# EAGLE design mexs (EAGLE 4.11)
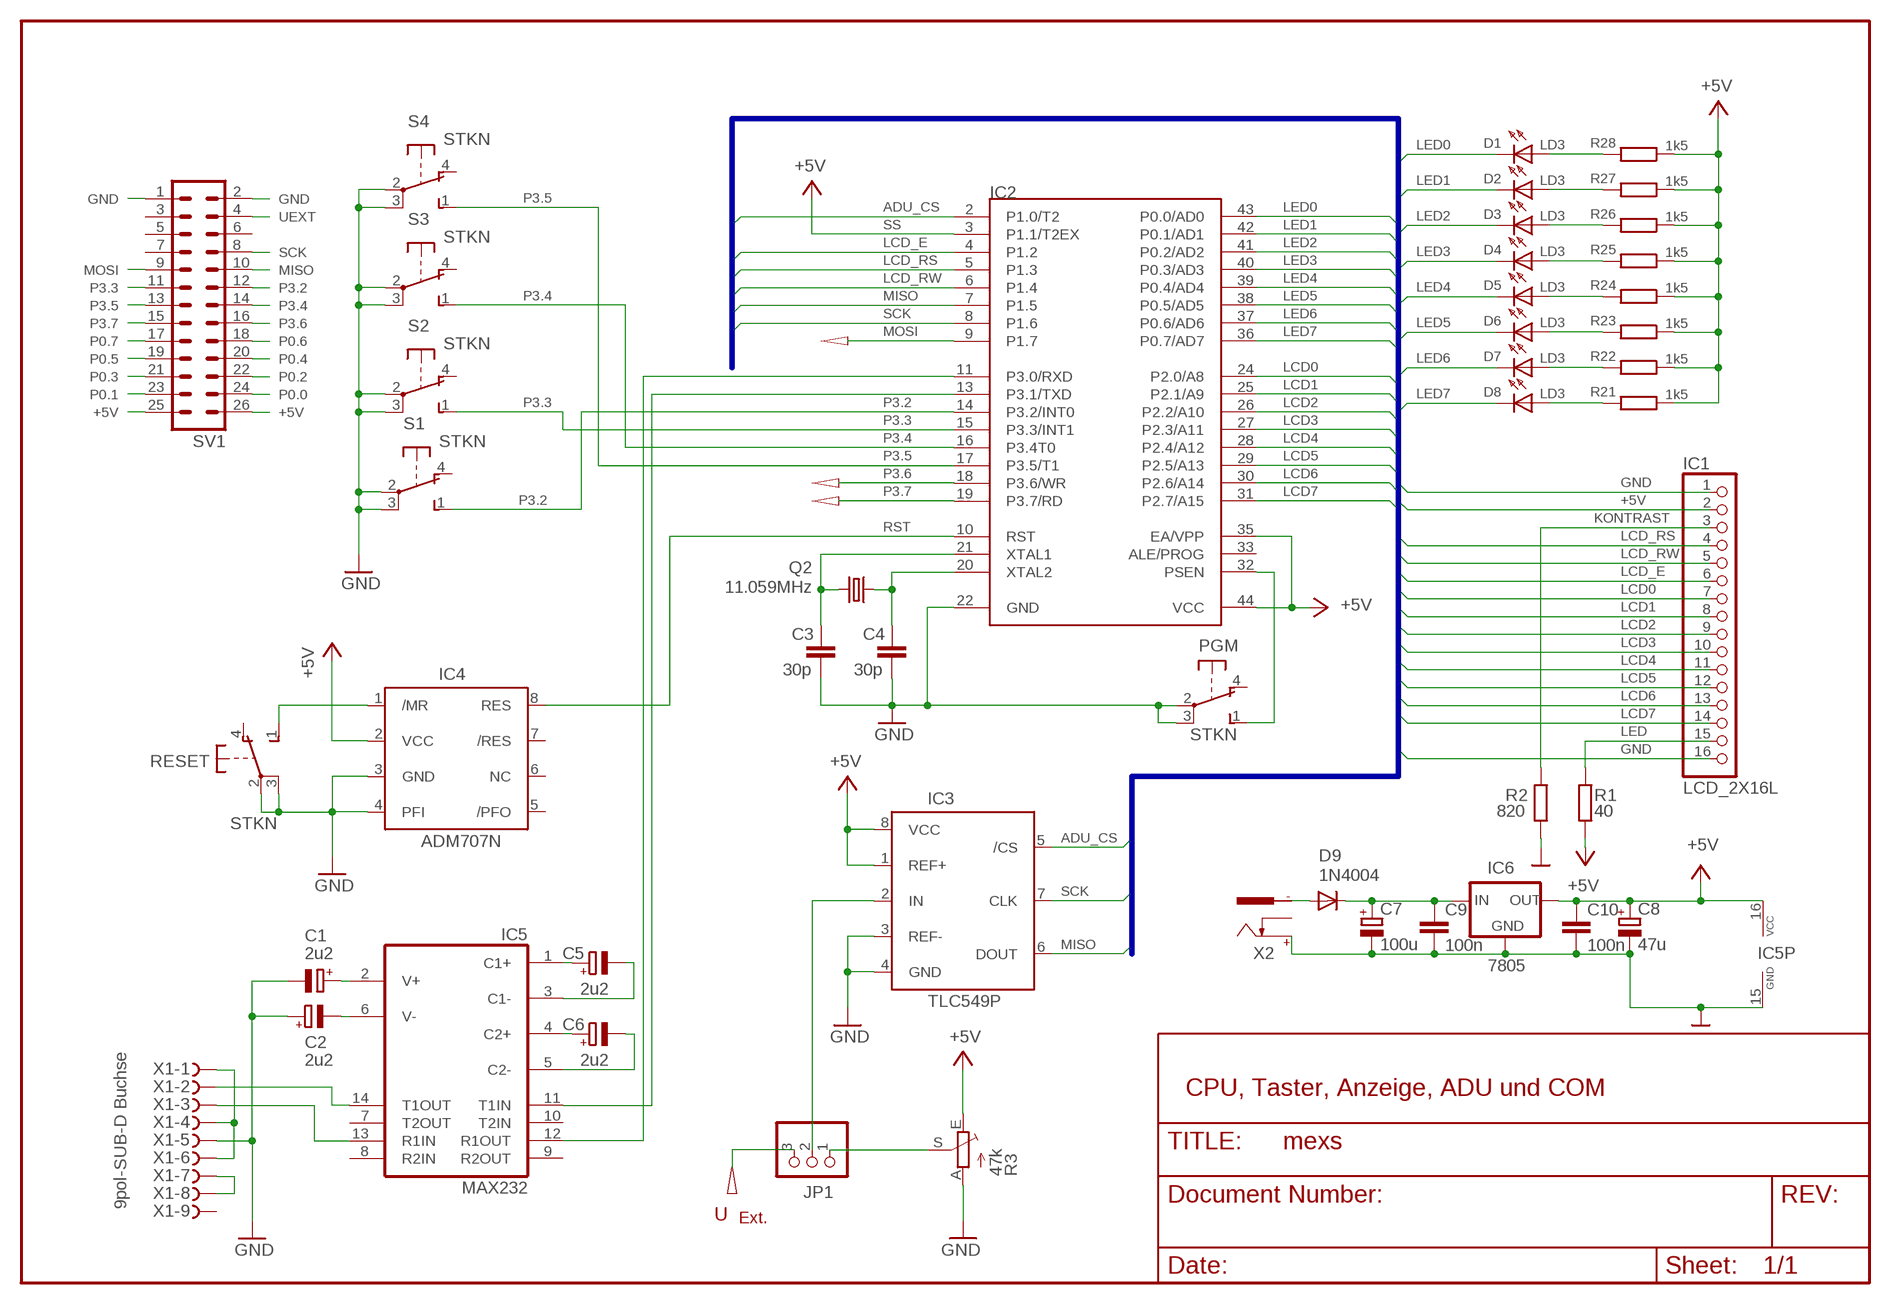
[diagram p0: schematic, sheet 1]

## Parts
C1  2u2  CPOL-EUE2.5-5  [E2,5-5]
C2  2u2  CPOL-EUE2.5-5  [E2,5-5]
C3  30p  C-EU025-024X044  [C025-024X044]
C4  30p  C-EU025-024X044  [C025-024X044]
C5  2u2  CPOL-EUE2.5-5  [E2,5-5]
C6  2u2  CPOL-EUE2.5-5  [E2,5-5]
C7  100u  CPOL-EUE5-10.5  [E5-10,5]
C8  47u  CPOL-EUE5-10.5  [E5-10,5]
C9  100n  C-EU050-025X075  [C050-025X075]
C10  100n  C-EU050-025X075  [C050-025X075]
D1  LD3  LED3MM  [LED3MM]
D2  LD3  LED3MM  [LED3MM]
D3  LD3  LED3MM  [LED3MM]
D4  LD3  LED3MM  [LED3MM]
D5  LD3  LED3MM  [LED3MM]
D6  LD3  LED3MM  [LED3MM]
D7  LD3  LED3MM  [LED3MM]
D8  LD3  LED3MM  [LED3MM]
D9  1N4004  [DO41-10]
IC1  LCD_2X16L  [LCD2X16]
IC2  AT89C55P  [PLCC44PA]
IC3  TLC549P  [DIL08]
IC4  ADM707N  [DIL08]
IC5  MAX232  [DIL16]
IC6  7805  78XXL  [78XXL]
JP1  PINHD-1X3  [1X03]
PGM  STKN  [STK-SCHMAL]
Q2  11.059MHz  CRYTALHC49U-V  [HC49U-V]
R1  40  R-EU_0207/7FETT  [0207/7FETT]
R2  820  R-EU_0207/7FETT  [0207/7FETT]
R3  47k  TRIM_EU-LI15  [LI15]
R21  1k5  R-EU_0207/7  [0207/7]
R22  1k5  R-EU_0207/7  [0207/7]
R23  1k5  R-EU_0207/7  [0207/7]
R24  1k5  R-EU_0207/7  [0207/7]
R25  1k5  R-EU_0207/7  [0207/7]
R26  1k5  R-EU_0207/7  [0207/7]
R27  1k5  R-EU_0207/7  [0207/7]
R28  1k5  R-EU_0207/7  [0207/7]
RESET  STKN  [STK-SCHMAL]
S1  STKN  [STK-SCHMAL]
S2  STKN  [STK-SCHMAL]
S3  STKN  [STK-SCHMAL]
S4  STKN  [STK-SCHMAL]
SV1  ML26  [ML26]
X1  9pol-SUB-D Buchse  F09HS  [F09H]
X2  737992-55  [737992-5]

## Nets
+5V: C8.+ C10.1 IC1.2 IC2.3(P1.1/T2EX) IC2.35(EA/VPP) IC2.44(VCC) IC3.1(REF+) IC3.8(VCC) IC4.2(VCC) IC5.16(VCC) IC6.OUT R1.1 R3.E R21.1 R22.1 R23.1 R24.1 R25.1 R26.1 R27.1 R28.1 SV1.25 SV1.26
ADU_CS: IC2.2(P1.0/T2) IC3.5(/CS)
GND: C1.- C2.+ C3.2 C4.2 C7.- C8.- C9.2 C10.2 IC1.1 IC1.16 IC2.22(GND) IC3.3(REF-) IC3.4(GND) IC4.3(GND) IC4.4(PFI) IC5.15(GND) IC6.GND PGM.2(P) PGM.3(P) R2.1 R3.A RESET.2(P) RESET.3(P) S1.2(P) S1.3(P) S2.2(P) S2.3(P) S3.2(P) S3.3(P) S4.2(P) S4.3(P) SV1.1 SV1.2 X1.5 X2.+
KONTRAST: IC1.3 R2.2
LCD0: IC1.7 IC2.24(P2.0/A8)
LCD1: IC1.8 IC2.25(P2.1/A9)
LCD2: IC1.9 IC2.26(P2.2/A10)
LCD3: IC1.10 IC2.27(P2.3/A11)
LCD4: IC1.11 IC2.28(P2.4/A12)
LCD5: IC1.12 IC2.29(P2.5/A13)
LCD6: IC1.13 IC2.30(P2.6/A14)
LCD7: IC1.14 IC2.31(P2.7/A15)
LCD_E: IC1.6 IC2.4(P1.2)
LCD_RS: IC1.4 IC2.5(P1.3)
LCD_RW: IC1.5 IC2.6(P1.4)
LED: IC1.15 R1.2
LED0: D1.K(C) IC2.43(P0.0/AD0) SV1.24
LED1: D2.K(C) IC2.42(P0.1/AD1) SV1.23
LED2: D3.K(C) IC2.41(P0.2/AD2) SV1.22
LED3: D4.K(C) IC2.40(P0.3/AD3) SV1.21
LED4: D5.K(C) IC2.39(P0.4/AD4) SV1.20
LED5: D6.K(C) IC2.38(P0.5/AD5) SV1.19
LED6: D7.K(C) IC2.37(P0.6/AD6) SV1.18
LED7: D8.K(C) IC2.36(P0.7/AD7) SV1.17
MISO: IC2.7(P1.5) IC3.6(DOUT) SV1.10
MOSI: IC2.9(P1.7) SV1.9
N$1: C3.1 IC2.21(XTAL1) Q2.2
N$2: C4.1 IC2.20(XTAL2) Q2.1
N$3: X1.1 X1.4 X1.6
N$4: IC4.1(/MR) RESET.1(S)
N$5: IC3.2(IN) JP1.2
N$6: D9.A X2.-1
N$7: IC2.32(PSEN) PGM.1(S)
N$8: D8.A R21.2
N$9: X1.7 X1.8
N$10: C7.+ C9.1 D9.C IC6.IN
N$11: IC5.14(T1OUT) X1.2
N$12: IC5.13(R1IN) X1.3
N$13: D7.A R22.2
N$14: D6.A R23.2
N$15: IC2.11(P3.0/RXD) IC5.12(R1OUT)
N$16: D5.A R24.2
N$17: D4.A R25.2
N$18: D3.A R26.2
N$19: D2.A R27.2
N$20: D1.A R28.2
N$21: IC2.13(P3.1/TXD) IC5.11(T1IN)
N$22: C5.+ IC5.1(C1+)
N$23: C6.+ IC5.4(C2+)
N$24: C5.- IC5.3(C1-)
N$25: C6.- IC5.5(C2-)
N$26: C2.- IC5.6(V-)
N$27: C1.+ IC5.2(V+)
N$28: JP1.1 R3.S
P3.2: IC2.14(P3.2/INT0) S1.1(S) SV1.12
P3.3: IC2.15(P3.3/INT1) S2.1(S) SV1.11
P3.4: IC2.16(P3.4T0) S3.1(S) SV1.14
P3.5: IC2.17(P3.5/T1) S4.1(S) SV1.13
P3.6: IC2.18(P3.6/WR) SV1.16
P3.7: IC2.19(P3.7/RD) SV1.15
RST: IC2.10(RST) IC4.8(RES)
SCK: IC2.8(P1.6) IC3.7(CLK) SV1.8
UEXT: JP1.3 SV1.4
Unconnected: IC2.33(ALE/PROG) IC4.5(/PFO) IC4.6(NC) IC4.7(/RES) IC5.7(T2OUT) IC5.8(R2IN) IC5.9(R2OUT) IC5.10(T2IN) PGM.4(O) RESET.4(O) S1.4(O) S2.4(O) S3.4(O) S4.4(O) SV1.3 SV1.5 SV1.6 SV1.7 X1.9 X2.-2 X2.K

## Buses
LCD[0..7],LCD_E,LCD_RS,LCD_RW,+5V,GND,SCK,MOSI,MISO,RES,LED[0..7],P1.[0..7]

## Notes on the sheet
- SS
- P0.7 | P0.6
- P0.5 | P0.4
- P0.3 | P0.2
- P0.1 | P0.0
- CPU, Taster, Anzeige, ADU und COM
- Ext.
- U

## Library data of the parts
C1 C2 C5-C8 = rcl:CPOL-EU: POLARIZED CAPACITOR, European symbol
C3 C4 C9 C10 = rcl:C-EU: CAPACITOR, European symbol
D1-D8 = led:LED3MM: LED
D9 = diode:1N4004: DIODE
IC1 = display-lcd:LCD_2X16: LC-Display mit 2 Zeilen a 16 Zeichen. Anschluss per 14 poligem Standard-Interface.
IC2 = atmel89cxxxx:AT89C55P
IC3 = linear:TLC549: 8-Bit Analog-Digital Umsetzer mit SPI-Schnittstelle, 5 V, CMOS
IC4 = analog-devices:ADM707: uC Supervisor
IC5 = maxim:MAX232: RS232 TRANSEIVER
IC6 = v-reg:78XXL: VOLTAGE REGULATOR
JP1 = pinhead:PINHD-1X3: PIN HEADER
PGM RESET S1-S4 = switch-misc:STK: SWITCH
Q2 = crystal:CRYTAL: CRYSTAL
R1 R2 R21-R28 = rcl:R-EU_: RESISTOR, European symbol
R3 = pot:TRIM_EU-: POTENTIOMETER
SV1 = con-ml:ML26: HARTING
X1 = con-subd:F09?S: SUB-D
X2 = con-conrad:737992-55: FEMALE PRINT CONNECTOR DIN 45323 (34V/3A), ROKA, distributor Conrad

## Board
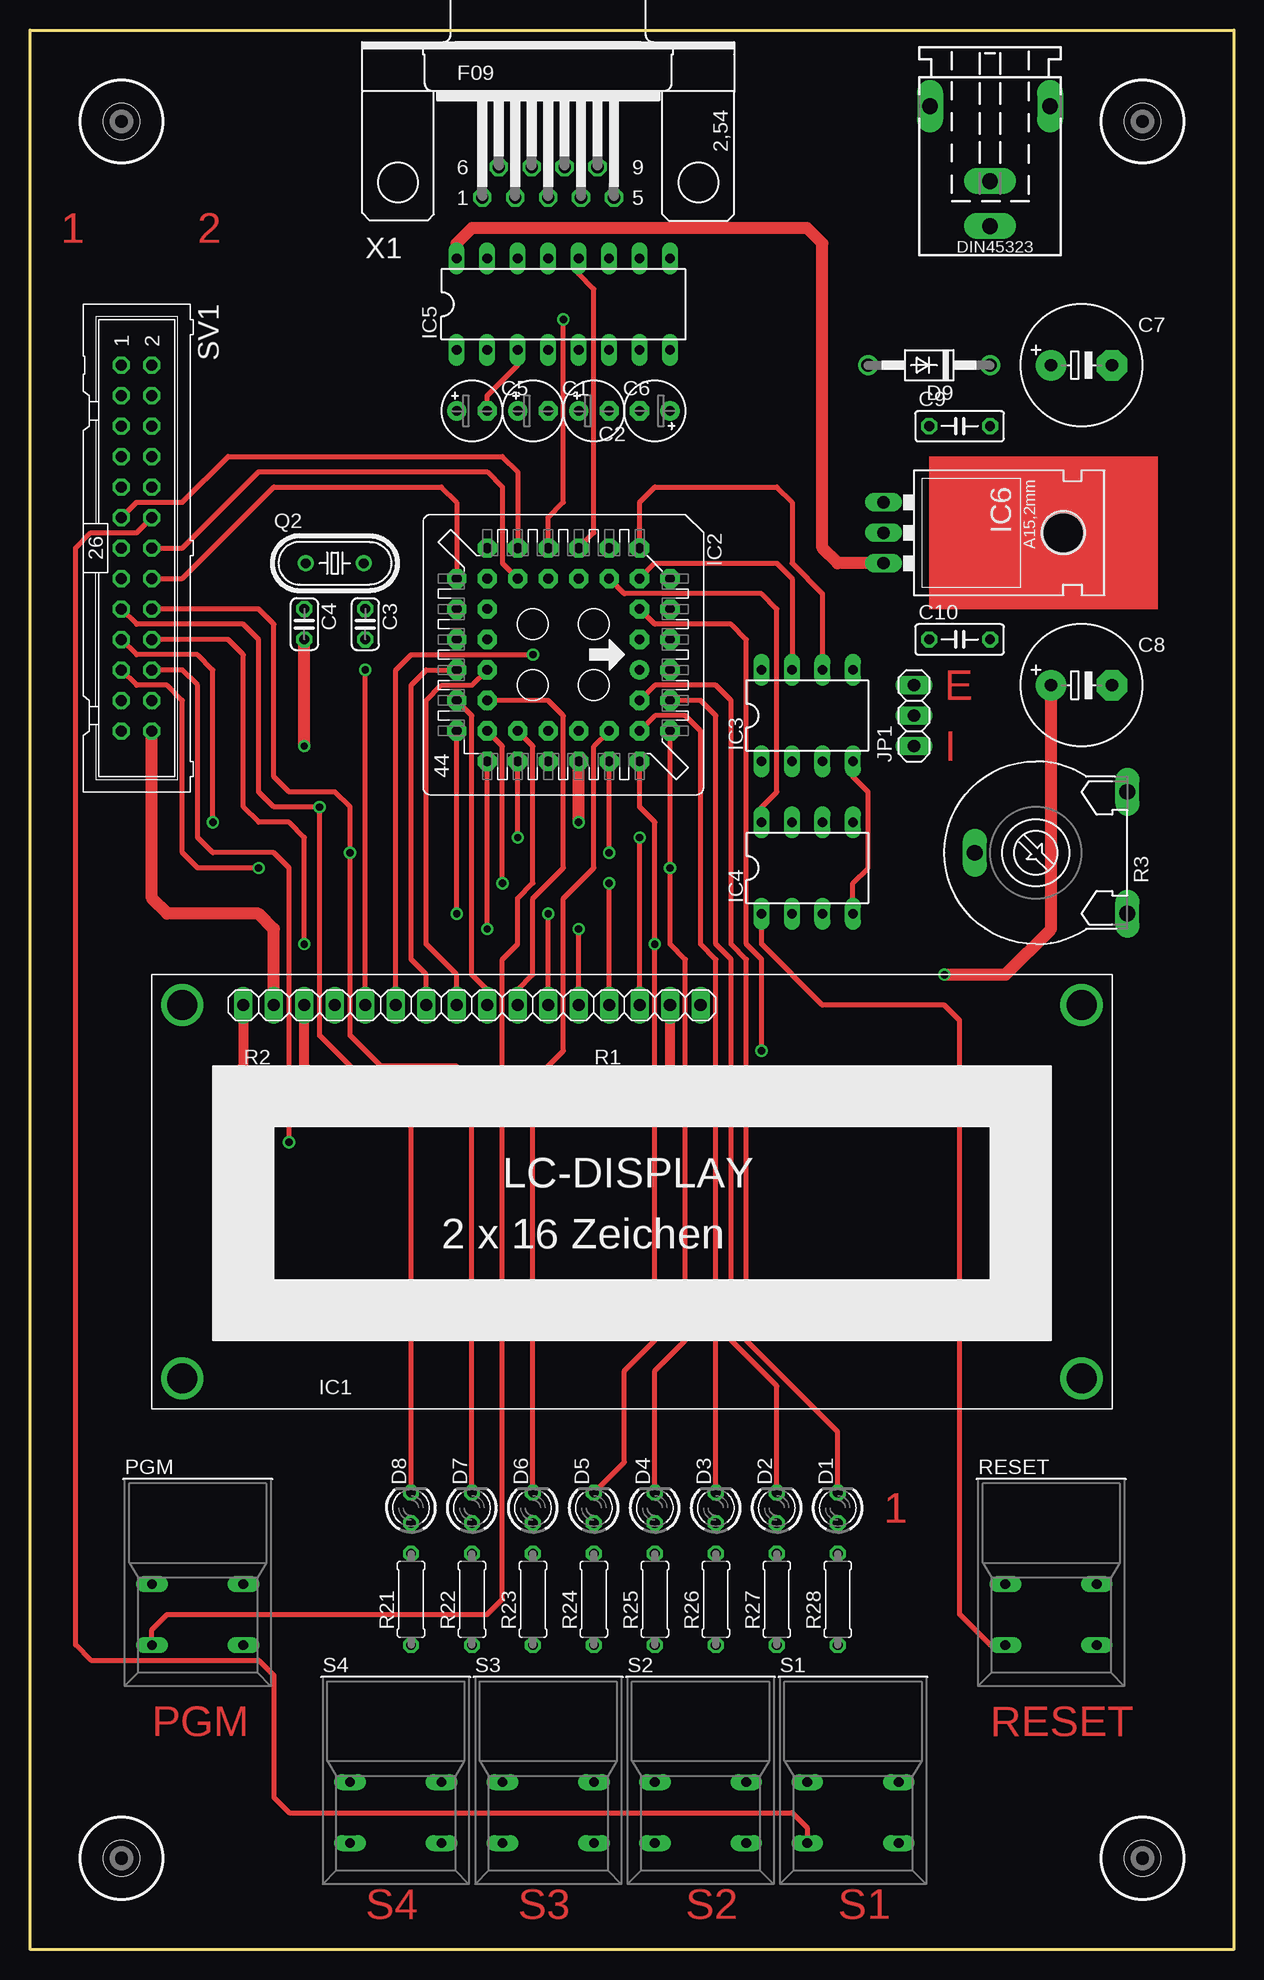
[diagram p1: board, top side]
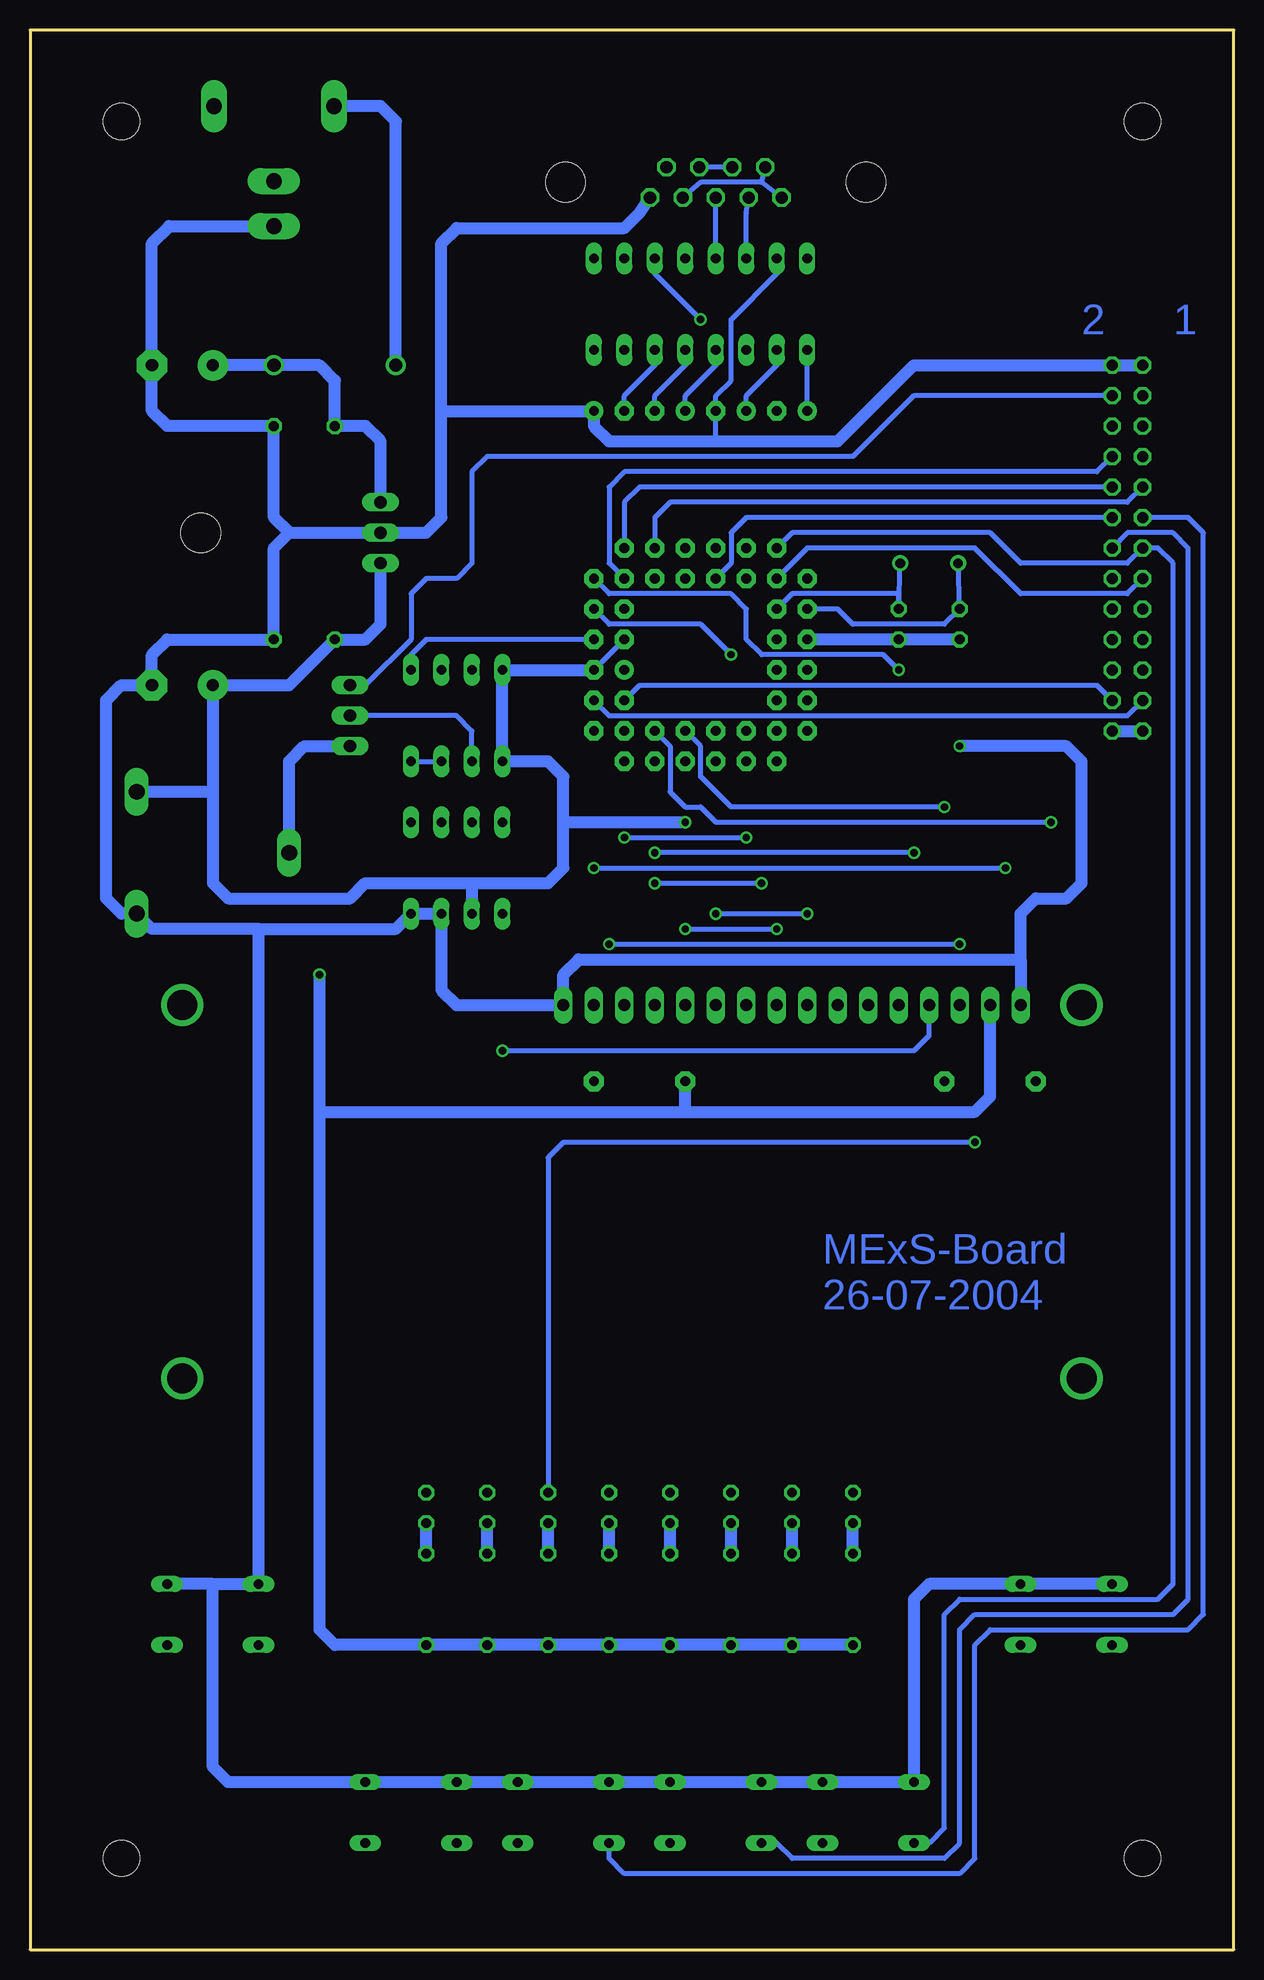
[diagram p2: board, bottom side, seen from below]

Size 100.33 x 160.02 mm. Coordinates in mm from the lower left corner, seen from the top.
Outline: 0,0 0,160.02 100.33,160.02 100.33,0 0,0
Copper layers (1*16): Top 0.035mm / dielectric 1.5mm / Bottom 0.035mm
Design rules "default": minimum track width 16mil, minimum drill 24mil, track to track 8mil, track to pad 8mil, pad to pad 8mil, via to via 8mil, smd to smd 8mil, copper to edge 40mil, drill to drill 8mil, minimum pad ring 10mil, minimum via ring 8mil, stop-mask expansion 4mil, vias tented up to drill 0mil, thermal gap 10mil

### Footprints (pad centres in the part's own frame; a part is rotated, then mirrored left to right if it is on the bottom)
E2,5-5 = drill 0.813 pad 1.6 round: + -1.27,0 | drill 0.813 pad 1.6 octagon: - 1.27,0
C025-024X044 = drill 0.813 octagon: 1 -1.27,0; 2 1.27,0
E5-10,5 = drill 1.016 pad 2.54 round: + -2.54,0 | drill 1.016 pad 2.54 octagon: - 2.54,0
C050-025X075 = drill 0.813 octagon: 1 -2.54,0; 2 2.54,0
LED3MM = drill 0.813 octagon: A -1.27,0; K 1.27,0
DO41-10 = drill 1.118 round: A 5.08,0; C -5.08,0
LCD2X16 = drill 1.016 long: 1 -20.32,7.62; 2 -17.78,7.62; 3 -15.24,7.62; 4 -12.7,7.62; 5 -10.16,7.62; 6 -7.62,7.62; 7 -5.08,7.62; 8 -2.54,7.62; 9 0,7.62; 10 2.54,7.62; 11 5.08,7.62; 12 7.62,7.62; 13 10.16,7.62; 14 12.7,7.62; 15 15.24,7.62; 16 17.78,7.62 | drill 2.5 round: P$1 -25.4,7.62; P$2 49.53,7.62; P$3 -25.4,-23.495; P$4 49.53,-23.495
PLCC44PA = drill 0.813 pad 1.6 round: 1 1.27,6.35 | drill 0.813 pad 1.6 octagon: 2 -1.27,8.89; 3 -1.27,6.35; 4 -3.81,8.89; 5 -3.81,6.35; 6 -6.35,8.89; 7 -8.89,6.35; 8 -6.35,6.35; 9 -8.89,3.81; 10 -6.35,3.81; 11 -8.89,1.27; 12 -6.35,1.27; 13 -8.89,-1.27; 14 -6.35,-1.27; 15 -8.89,-3.81; 16 -6.35,-3.81; 17 -8.89,-6.35; 18 -6.35,-8.89; 19 -6.35,-6.35; 20 -3.81,-8.89; 21 -3.81,-6.35; 22 -1.27,-8.89; 23 -1.27,-6.35; 24 1.27,-8.89; 25 1.27,-6.35; 26 3.81,-8.89; 27 3.81,-6.35; 28 6.35,-8.89; 29 8.89,-6.35; 30 6.35,-6.35; 31 8.89,-3.81; 32 6.35,-3.81; 33 8.89,-1.27; 34 6.35,-1.27; 35 8.89,1.27; 36 6.35,1.27; 37 8.89,3.81; 38 6.35,3.81; 39 8.89,6.35; 40 6.35,8.89; 41 6.35,6.35; 42 3.81,8.89; 43 3.81,6.35; 44 1.27,8.89
DIL08 = drill 0.813 long: 1 -3.81,-3.81; 2 -1.27,-3.81; 3 1.27,-3.81; 4 3.81,-3.81; 5 3.81,3.81; 6 1.27,3.81; 7 -1.27,3.81; 8 -3.81,3.81
DIL16 = drill 0.813 long: 1 -8.89,-3.81; 2 -6.35,-3.81; 3 -3.81,-3.81; 4 -1.27,-3.81; 5 1.27,-3.81; 6 3.81,-3.81; 7 6.35,-3.81; 8 8.89,-3.81; 9 8.89,3.81; 10 6.35,3.81; 11 3.81,3.81; 12 1.27,3.81; 13 -1.27,3.81; 14 -3.81,3.81; 15 -6.35,3.81; 16 -8.89,3.81
78XXL = drill 1.016 long: GND 0,-3.81; IN -2.54,-3.81; OUT 2.54,-3.81 | hole 3.302: 0,11.176
1X03 = drill 1.016 long: 1 -2.54,0; 2 0,0; 3 2.54,0
STK-SCHMAL = drill 0.813 long: 1 -3.81,-2.54; 2 -3.81,2.54; 3 3.81,2.54; 4 3.81,-2.54
HC49U-V = drill 0.813 round: 1 -2.413,0; 2 2.413,0
0207/7FETT = drill 0.813 pad 1.676 octagon: 1 -3.81,0; 2 3.81,0
LI15 = drill 1.321 long: A -5.08,-7.62; E 5.08,-7.62; S 0,5.08
0207/7 = drill 0.813 octagon: 1 -3.81,0; 2 3.81,0
ML26 = drill 0.914 octagon: 1 -15.24,-1.27; 2 -15.24,1.27; 3 -12.7,-1.27; 4 -12.7,1.27; 5 -10.16,-1.27; 6 -10.16,1.27; 7 -7.62,-1.27; 8 -7.62,1.27; 9 -5.08,-1.27; 10 -5.08,1.27; 11 -2.54,-1.27; 12 -2.54,1.27; 13 0,-1.27; 14 0,1.27; 15 2.54,-1.27; 16 2.54,1.27; 17 5.08,-1.27; 18 5.08,1.27; 19 7.62,-1.27; 20 7.62,1.27; 21 10.16,-1.27; 22 10.16,1.27; 23 12.7,-1.27; 24 12.7,1.27; 25 15.24,-1.27; 26 15.24,1.27
DRIL-3 = hole 3: 0,0
F09H = drill 1.016 octagon: 1 -5.486,-1.27; 2 -2.743,-1.27; 3 0,-1.27; 4 2.743,-1.27; 5 5.486,-1.27; 6 -4.115,1.27; 7 -1.372,1.27; 8 1.372,1.27; 9 4.115,1.27 | hole 3.302: -12.522,0; 12.522,0
737992-5 = drill 1.3 pad 2.184 long: + 0,10; -1 5,0; -2 -5,0; K 0,6.25

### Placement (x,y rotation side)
C1  41.91,128.27 0 top
C2  52.07,128.27 180 top
C3  27.94,110.49 270 top
C4  22.86,110.49 270 top
C5  36.83,128.27 0 top
C6  46.99,128.27 0 top
C7  87.63,132.08 0 top
C8  87.63,105.41 0 top
C9  77.47,127 0 top
C10  77.47,109.22 0 top
D1  67.31,36.83 90 top
D2  62.23,36.83 90 top
D3  57.15,36.83 90 top
D4  52.07,36.83 90 top
D5  46.99,36.83 90 top
D6  41.91,36.83 90 top
D7  36.83,36.83 90 top
D8  31.75,36.83 90 top
D9  74.93,132.08 180 top
IC1  38.1,71.12 0 top
IC2  44.45,107.95 270 top
IC3  64.77,102.87 0 top
IC4  64.77,90.17 0 top
IC5  44.45,137.16 0 top
IC6  74.93,118.11 270 top
JP1  73.66,102.87 90 top
PGM  13.97,27.94 0 top
Q2  25.4,115.57 0 top
R1  49.53,72.39 0 top
R2  20.32,72.39 0 top
R3  83.82,91.44 90 top
R21  31.75,29.21 90 top
R22  36.83,29.21 90 top
R23  41.91,29.21 90 top
R24  46.99,29.21 90 top
R25  52.07,29.21 90 top
R26  57.15,29.21 90 top
R27  62.23,29.21 90 top
R28  67.31,29.21 90 top
RESET  85.09,27.94 0 top
S1  68.58,11.43 0 top
S2  55.88,11.43 0 top
S3  43.18,11.43 0 top
S4  30.48,11.43 0 top
SV1  8.89,116.84 270 top
U$4  [DRIL-3]  92.71,7.62 270 top
U$5  [DRIL-3]  7.62,7.62 270 top
U$6  [DRIL-3]  7.62,152.4 270 top
U$7  [DRIL-3]  92.71,152.4 270 top
X1  43.18,147.32 0 top
X2  80.01,153.67 180 top

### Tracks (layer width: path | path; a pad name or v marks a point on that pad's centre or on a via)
+5V  (via drill 0.61)
  Top 1.016: IC5.16 35.56,142.24 36.83,143.51 64.77,143.51 66.04,142.24 66.04,116.84 67.31,115.57 IC6.OUT | v76.2,81.28 81.28,81.28 85.09,85.09 C8.+ | v45.72,93.98 IC2.35 | IC1.2 20.32,85.09 19.05,86.36 11.43,86.36 10.16,87.63 SV1.26
  Bottom 0.406: IC2.44 IC2.3
  Bottom 1.016: 85.09,96.52 R3.E | 85.09,96.52 C8.+ 78.74,105.41 C10.1 72.39,109.22 71.12,110.49 IC6.OUT | 63.5,88.9 IC4.2 | 55.88,93.98 55.88,90.17 57.15,88.9 63.5,88.9 | R21.1 R22.1 R23.1 R24.1 | R24.1 R25.1 | R25.1 R26.1 | R26.1 R27.1 | R27.1 R28.1 | R24.1 R25.1 | R25.1 R26.1 | R26.1 R27.1 | R27.1 R28.1 | R28.1 74.93,25.4 76.2,26.67 76.2,69.85 | 76.2,69.85 v76.2,81.28 | 45.72,69.85 R1.1 | 76.2,69.85 45.72,69.85 | SV1.26 SV1.25 | 55.88,93.98 v45.72,93.98 | 55.88,93.98 55.88,97.79 57.15,99.06 IC3.1 IC3.8 IC2.44 | 45.72,69.85 21.59,69.85 20.32,71.12 IC1.2 | 63.5,88.9 72.39,88.9 73.66,87.63 83.82,87.63 85.09,88.9 85.09,96.52
ADU_CS
  Bottom 0.406: IC2.2 67.31,109.22 68.58,107.95 IC3.5
GND  (via drill 0.61)
  Top 0.406: IC4.4 68.58,88.9 69.85,90.17 69.85,96.52 68.58,97.79 IC3.4
  Top 0.813: R2.1 17.78,73.66 IC1.1
  Top 1.016: v22.86,100.33 C4.2
  Bottom 0.406: IC3.4 IC3.3 | 43.18,125.73 C1.- 43.18,129.54 41.91,130.81 41.91,135.89 38.1,139.7 IC5.15 | IC2.22 C3.2 C4.2
  Bottom 1.016: X2.+ 88.74,143.67 90.17,142.24 C7.- 90.17,128.27 88.9,127 C9.2 80.01,119.38 78.74,118.11 | 78.74,118.11 IC6.GND 67.31,118.11 66.04,119.38 66.04,128.27 | 78.74,118.11 80.01,116.84 C10.2 88.9,109.22 90.17,107.95 C8.- 92.71,105.41 93.98,104.14 93.98,87.63 92.71,86.36 R3.A 90.17,85.09 81.28,85.09 | IC4.4 IC4.3 | 66.04,128.27 C2.+ 53.34,127 52.07,125.73 43.18,125.73 33.02,125.73 26.67,132.08 SV1.2 SV1.1 | X1.5 49.53,144.78 50.8,143.51 64.77,143.51 66.04,142.24 66.04,128.27 | 85.09,30.48 85.09,15.24 83.82,13.97 S1.3 S1.2 S2.3 S2.2 S3.3 S3.2 S4.3 S4.2 26.67,29.21 25.4,30.48 PGM.3 PGM.2 | 85.09,30.48 RESET.3 | 85.09,30.48 RESET.2 81.28,85.09 | IC4.4 IC4.3 | 81.28,85.09 69.85,85.09 IC4.4 | 17.78,82.55 54.61,82.55 55.88,81.28 IC1.16 64.77,78.74 66.04,80.01 IC4.3 | 17.78,82.55 IC1.1 | C4.2 C3.2 IC2.22 | v22.86,100.33 13.97,100.33 12.7,99.06 12.7,88.9 13.97,87.63 16.51,87.63 17.78,86.36 17.78,82.55
KONTRAST
  Top 0.813: R2.2 22.86,73.66 IC1.3
LCD0
  Top 0.406: IC2.24 33.02,106.68 31.75,105.41 31.75,82.55 33.02,81.28 IC1.7
LCD1
  Top 0.406: IC2.25 36.83,105.41 34.29,105.41 33.02,104.14 33.02,83.82 35.56,81.28 IC1.8
LCD2
  Top 0.406: IC2.26 36.83,102.87 36.83,81.28 38.1,80.01 IC1.9
LCD3
  Top 0.406: IC2.27 43.18,104.14 44.45,102.87 44.45,90.17 41.91,87.63 41.91,81.28 40.64,80.01 IC1.10
LCD4  (via drill 0.61)
  Top 0.406: v35.56,86.36 IC2.28 | IC1.11 v43.18,86.36
  Bottom 0.406: v43.18,86.36 v35.56,86.36
LCD5  (via drill 0.61)
  Top 0.406: v38.1,85.09 IC2.29 | IC1.12 v45.72,85.09
  Bottom 0.406: v45.72,85.09 v38.1,85.09
LCD6  (via drill 0.61)
  Top 0.406: v39.37,88.9 39.37,100.33 IC2.30 | IC1.13 v48.26,88.9
  Bottom 0.406: v48.26,88.9 v39.37,88.9
LCD7  (via drill 0.61)
  Top 0.406: v40.64,92.71 IC2.31 | IC1.14 v50.8,92.71
  Bottom 0.406: v50.8,92.71 v40.64,92.71
LCD_E  (via drill 0.61)
  Top 0.406: v41.91,107.95 31.75,107.95 30.48,106.68 IC1.6
  Bottom 0.406: v41.91,107.95 44.45,110.49 52.07,110.49 IC2.4
LCD_RS  (via drill 0.61)
  Top 0.406: IC2.5 52.07,110.49 58.42,110.49 59.69,109.22 59.69,83.82 60.96,82.55 v60.96,74.93
  Bottom 0.406: v60.96,74.93 26.67,74.93 25.4,76.2 IC1.4
LCD_RW  (via drill 0.61)
  Top 0.406: IC1.5 v27.94,106.68
  Bottom 0.406: IC2.6 52.07,113.03 41.91,113.03 40.64,111.76 40.64,109.22 39.37,107.95 29.21,107.95 v27.94,106.68
LED
  Top 0.813: R1.2 IC1.15
LED0
  Top 0.406: D1.K 67.31,43.18 59.69,50.8 59.69,82.55 58.42,83.82 58.42,104.14 57.15,105.41 52.07,105.41 IC2.43
  Bottom 0.406: SV1.24 11.43,105.41 49.53,105.41 IC2.43
LED1
  Top 0.406: D2.K 62.23,46.99 58.42,50.8 58.42,82.55 57.15,83.82 57.15,102.87 55.88,104.14 IC2.42
  Bottom 0.406: SV1.23 8.89,102.87 52.07,102.87 IC2.42
LED2  (via drill 0.61)
  Top 0.406: D3.K 57.15,82.55 55.88,83.82 55.88,101.6 54.61,102.87 52.07,102.87 IC2.41 | SV1.22 12.7,106.68 13.97,105.41 13.97,92.71 15.24,91.44 20.32,91.44 21.59,90.17 v21.59,67.31
  Bottom 0.406: v21.59,67.31 55.88,67.31 57.15,66.04 D3.K
LED3  (via drill 0.61)
  Top 0.406: D4.K 52.07,48.26 54.61,50.8 54.61,82.55 53.34,83.82 v53.34,90.17 IC2.40 | SV1.21 8.89,105.41 11.43,105.41 12.7,104.14 12.7,91.44 13.97,90.17 v19.05,90.17
  Bottom 0.406: v53.34,90.17 v19.05,90.17
LED4  (via drill 0.61)
  Top 0.406: D5.K 49.53,40.64 49.53,48.26 52.07,50.8 v52.07,83.82 52.07,93.98 50.8,95.25 IC2.39 | SV1.20 16.51,109.22 17.78,107.95 17.78,95.25 19.05,93.98 21.59,93.98 22.86,92.71 v22.86,83.82
  Bottom 0.406: v52.07,83.82 v22.86,83.82
LED5  (via drill 0.61)
  Top 0.406: v15.24,93.98 15.24,106.68 13.97,107.95 8.89,107.95 SV1.19 | D6.K 41.91,72.39 44.45,74.93 44.45,87.63 46.99,90.17 46.99,100.33 IC2.38
  Bottom 0.406: IC2.38 46.99,100.33 46.99,96.52 45.72,95.25 44.45,95.25 43.18,93.98 v15.24,93.98
LED6  (via drill 0.61)
  Top 0.406: D7.K 36.83,72.39 35.56,73.66 29.21,73.66 26.67,76.2 v26.67,91.44 26.67,95.25 25.4,96.52 21.59,96.52 20.32,97.79 20.32,110.49 19.05,111.76 SV1.18 | v48.26,91.44 IC2.37
  Bottom 0.406: v26.67,91.44 v48.26,91.44
LED7  (via drill 0.61)
  Top 0.406: D8.K 31.75,68.58 24.13,76.2 v24.13,95.25 20.32,95.25 19.05,96.52 19.05,109.22 17.78,110.49 8.89,110.49 SV1.17
  Bottom 0.406: IC2.36 44.45,100.33 44.45,97.79 41.91,95.25 v24.13,95.25
MISO
  Top 0.406: IC2.7 50.8,120.65 52.07,121.92 62.23,121.92 63.5,120.65 63.5,115.57 66.04,113.03 IC3.6
  Bottom 0.406: SV1.10 49.53,121.92 50.8,120.65 IC2.7
MOSI
  Bottom 0.406: SV1.9 8.89,120.65 46.99,120.65 48.26,119.38 IC2.9
N$1
  Bottom 0.406: Q2.2 C3.1 27.94,113.03 36.83,113.03 IC2.21
N$2
  Bottom 0.406: IC2.20 33.02,111.76 31.75,110.49 24.13,110.49 C4.1 Q2.1
N$3
  Bottom 0.406: X1.1 39.37,147.32 | 39.37,147.32 X1.6 | X1.4 44.45,147.32 39.37,147.32
N$4
  Top 0.406: RESET.1 80.01,25.4 77.47,27.94 77.47,77.47 76.2,78.74 66.04,78.74 60.96,83.82 IC4.1
N$5
  Bottom 0.406: IC3.2 63.5,101.6 64.77,102.87 JP1.2
N$6
  Bottom 1.016: D9.A 69.85,152.4 71.12,153.67 X2.-1
N$7
  Top 0.406: IC2.32 41.91,100.33 41.91,88.9 40.64,87.63 40.64,83.82 39.37,82.55 39.37,29.21 38.1,27.94 11.43,27.94 10.16,26.67 PGM.1
N$8
  Bottom 1.016: R21.2 D8.A
N$9
  Bottom 0.406: X1.7 X1.8
N$10
  Bottom 1.016: C7.+ D9.C 76.2,132.08 74.93,130.81 C9.1 72.39,127 71.12,125.73 IC6.IN
N$11
  Bottom 0.406: X1.2 40.64,144.78 IC5.14
N$12
  Bottom 0.406: IC5.13 X1.3
N$13
  Bottom 1.016: R22.2 D7.A
N$14
  Bottom 1.016: R23.2 D6.A
N$15
  Top 0.406: IC2.11 46.99,118.11 46.99,138.43 45.72,139.7 IC5.12
N$16
  Bottom 1.016: R24.2 D5.A
N$17
  Bottom 1.016: R25.2 D4.A
N$18
  Bottom 1.016: R26.2 D3.A
N$19
  Bottom 1.016: R27.2 D2.A
N$20
  Bottom 1.016: R28.2 D1.A
N$21  (via drill 0.61)
  Top 0.406: v44.45,135.89 44.45,120.65 43.18,119.38 IC2.13
  Bottom 0.406: v44.45,135.89 48.26,139.7 IC5.11
N$22
  Bottom 0.406: C5.+ IC5.1
N$23
  Bottom 0.406: IC5.4 43.18,132.08 45.72,129.54 C6.+
N$24
  Top 0.406: IC5.3 40.64,132.08 38.1,129.54 C5.-
N$25
  Bottom 0.406: IC5.5 45.72,132.08 48.26,129.54 C6.-
N$26
  Bottom 0.406: IC5.6 48.26,132.08 50.8,129.54 C2.-
N$27
  Bottom 0.406: IC5.2 38.1,132.08 40.64,129.54 C1.+
N$28
  Bottom 1.016: R3.S 78.74,99.06 77.47,100.33 JP1.1
P3.2
  Top 0.406: S1.1 64.77,10.16 63.5,11.43 21.59,11.43 20.32,12.7 20.32,22.86 19.05,24.13 5.08,24.13 3.81,25.4 3.81,116.84 5.08,118.11 8.89,118.11 SV1.12
  Bottom 0.406: IC2.14 41.91,115.57 41.91,118.11 40.64,119.38 SV1.12
P3.3
  Top 0.406: IC2.15 40.64,123.19 39.37,124.46 16.51,124.46 12.7,120.65 8.89,120.65 SV1.11
  Bottom 0.406: S2.1 52.07,7.62 50.8,6.35 22.86,6.35 21.59,7.62 21.59,25.4 20.32,26.67 3.81,26.67 2.54,27.94 2.54,118.11 3.81,119.38 SV1.11
P3.4
  Top 0.406: SV1.14 12.7,116.84 19.05,123.19 38.1,123.19 39.37,121.92 39.37,115.57 IC2.16
  Bottom 0.406: S3.1 38.1,8.89 36.83,7.62 24.13,7.62 22.86,8.89 22.86,26.67 21.59,27.94 5.08,27.94 3.81,29.21 3.81,116.84 5.08,118.11 8.89,118.11 SV1.14
P3.5
  Bottom 0.406: IC2.17 36.83,118.11 20.32,118.11 17.78,115.57 8.89,115.57 SV1.13 6.35,116.84 5.08,115.57 5.08,30.48 6.35,29.21 22.86,29.21 24.13,27.94 24.13,10.16 25.4,8.89 S4.1
P3.6
  Top 0.406: SV1.16 12.7,114.3 20.32,121.92 34.29,121.92 35.56,120.65 IC2.18
P3.7
  Bottom 0.406: SV1.15 8.89,113.03 17.78,113.03 21.59,116.84 35.56,116.84 IC2.19
RST
  Top 0.406: IC2.10 49.53,113.03 60.96,113.03 62.23,111.76 62.23,96.52 60.96,95.25 IC4.8
SCK
  Top 0.406: IC2.8 52.07,115.57 62.23,115.57 63.5,114.3 IC3.7
  Bottom 0.406: SV1.8 11.43,123.19 50.8,123.19 52.07,121.92 52.07,115.57 IC2.8
UEXT
  Bottom 0.406: SV1.4 26.67,129.54 31.75,124.46 62.23,124.46 63.5,123.19 63.5,115.57 64.77,114.3 67.31,114.3 68.58,113.03 68.58,109.22 72.39,105.41 JP1.3
(copper drawn outside any net)
  shapes: Top area x1

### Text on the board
Top: 1 | 2 | E | I | 1 | PGM | RESET | S4 | S3 | S2 | S1
Bottom: 1 | 2 | MExS-Board | 26-07-2004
